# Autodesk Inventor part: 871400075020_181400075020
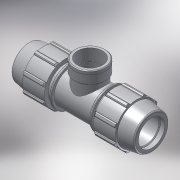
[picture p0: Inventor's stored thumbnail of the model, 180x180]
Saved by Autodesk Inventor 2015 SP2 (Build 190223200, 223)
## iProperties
Created: 2017-02
Part Number: 871400075020_181400075020
Material: PVC-Piping
Description: PLASSON TEE WITH THREADED FEMALE OFFTAKE 75-2"-75
Document SubType Name: Modeling
Designer: KIM
Mass: 92.6774 g
Surface Area: 199.44 cm^2
Volume: 66.1981 cm^3
Density: 1.4 g/cm^3
Appearance: Smooth - White
Author: KIM
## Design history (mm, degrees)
derived "87140.ipt"
feature "Solid1::87140.ipt"
feature "Solid2::87140.ipt"
tag "TaggingFeature1"
body "Solid1"
other parameters: "d2" = 75, "d4" = 15.41667, "d5" = 44.4, "d7" = 132, "d11" = 6.16667, "d13" = 120 deg, "d14" = 97.5, "d15" = 12 deg, "d16" = 114.84, "d18" = 3.75, "d19" = 35 deg, "d20" = 17.5 deg, "d21" = 122.76, "d23" = 0, "d25" = 360 deg, "d27" = 2.64, "d33" = 1.5, "d42" = 66.6, "d43" = 3.96, "d46" = 2.25, "d68" = 11.1, "d76" = 56.656, "d80" = 1.69968, "d91" = 99, "d93" = 137, "d95" = 67.5, "d115" = 70.82, "d116" = 135 deg, "d117" = 65.1544, "d119" = 67.5, "d121" = 0, "d122" = 50.625, "d124" = 0, "d128" = 0, "d129" = 7.5, "d130" = 9, "d131" = 0.3, "d132" = 0.3, "d133" = 70.82, "d_" = 75, "E_" = 132, "l_" = 137, "Rp_" = 56.656
